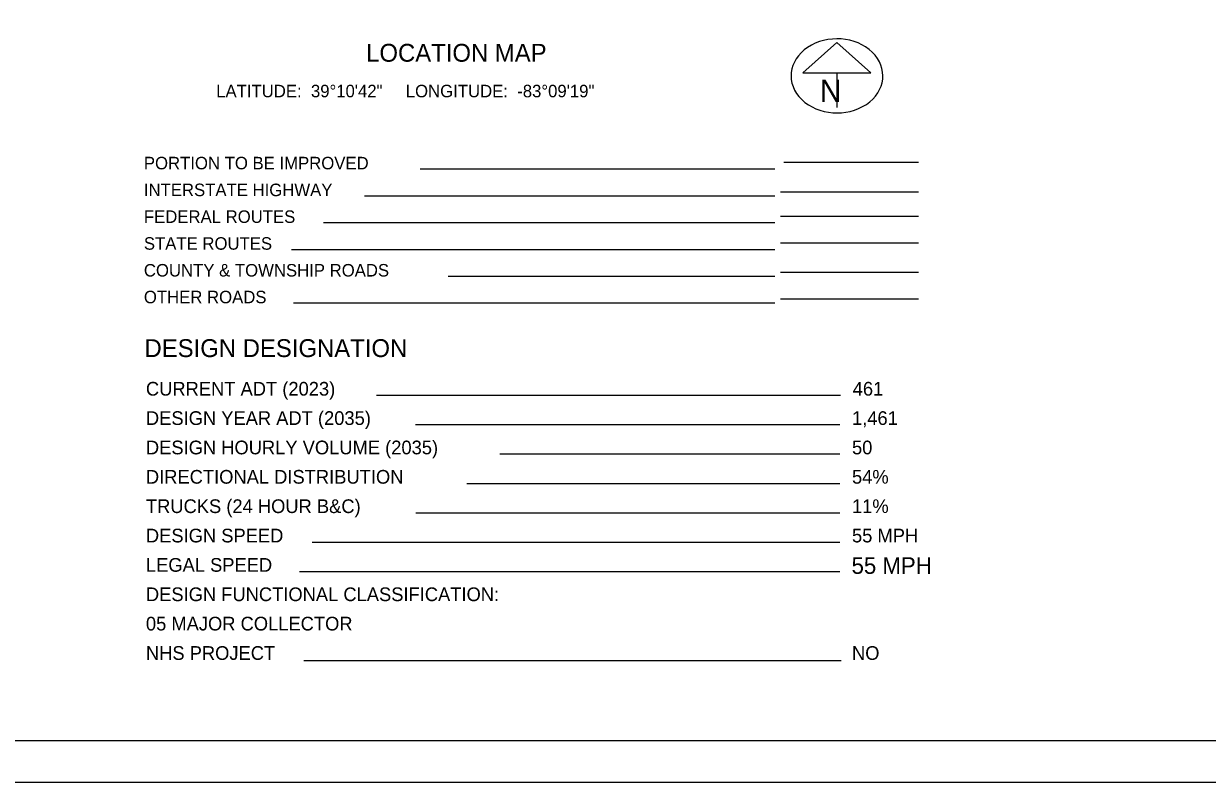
# Model space of a CAD drawing. Extents: x -139 to 835, y 0 to 440.
# Drawn here: x 62.7 to 348, y 0 to 182.8 of the extents above; entities that cross this region are included whole.
import ezdxf

# ---------------------------------------------------------------- set-up
doc = ezdxf.new("R2010")
doc.units = 0
for name, color, linetype in [('Default', 7, 'Continuous'), ('SH_Border', 7, 'Continuous'), ('SH_Cut_Line', 7, 'Continuous'), ('SH_Data', 7, 'Continuous'), ('SH_Text', 7, 'Continuous')]:
    doc.layers.add(name, color=color, linetype=linetype)

msp = doc.modelspace()

# ---------------------------------------------------------------- linework, layer by layer
at = {"layer": 'SH_Border'}
msp.add_lwpolyline([(30, 430), (670, 430), (670, 10), (30, 10)], close=True, dxfattribs=at)
at = {"layer": 'SH_Cut_Line'}
msp.add_lwpolyline([(0, 0), (680, 0), (680, 440), (0, 440)], close=True, dxfattribs=at)
at = {"layer": 'SH_Data'}
for p, q in [((258.73, 178.28), (250.53, 170.94)), ((266.93, 170.94), (258.73, 178.28)), ((250.53, 170.94), (266.93, 170.94)), ((258.73, 170.94), (258.73, 162.61)), ((258.73, 170.24), (258.73, 170.24)), ((258.73, 170.24), (258.73, 170.24)), ((245.95, 149.41), (278.4, 149.41)), ((243.75, 147.72), (158.3, 147.72)), ((243.75, 141.26), (144.86, 141.26)), ((278.4, 142.21), (245.08, 142.21)), ((243.75, 134.81), (134.99, 134.81)), ((278.4, 136.37), (245.08, 136.37)), ((278.4, 129.91), (245.08, 129.91)), ((243.75, 128.35), (127.25, 128.35)), ((278.4, 122.88), (245.08, 122.88)), ((243.75, 121.89), (165, 121.89)), ((243.75, 115.44), (127.74, 115.44)), ((278.4, 116.42), (245.08, 116.42)), ((259.55, 93.19), (147.78, 93.19)), ((259.39, 86.12), (157.16, 86.12)), ((259.39, 79.04), (177.46, 79.04)), ((259.39, 71.97), (169.5, 71.97)), ((259.39, 64.89), (157.19, 64.89)), ((259.39, 57.81), (132.22, 57.81)), ((259.39, 50.74), (129.15, 50.74)), ((259.73, 29.25), (130.22, 29.25))]:
    msp.add_line(p, q, dxfattribs=at)
msp.add_ellipse((258.73, 170.24), major_axis=(-11.06, 0), ratio=0.807538, start_param=5.406678, end_param=11.689575, dxfattribs=at)

# ---------------------------------------------------------------- texts
at = {"layer": 'Default'}
msp.add_text('55 MPH', height=4, dxfattribs=at).set_placement((262.25, 50.24))
at = {"layer": 'SH_Data'}
for s, height, p in [('N', 5.38, (254.59, 163.97)), ('DESIGN DESIGNATION', 4.3046, (91.83, 102.48))]:
    msp.add_text(s, height=height, dxfattribs=at).set_placement(p)
at = {"layer": 'SH_Text'}
for s, height, p in [('LOCATION MAP', 4.3046, (145.25, 173.65)), ('LATITUDE:  39°10\'42"     LONGITUDE:  -83°09\'19"', 3.0132, (109.11, 165.08)), ('PORTION TO BE IMPROVED', 3.0132, (91.68, 147.72)), ('INTERSTATE HIGHWAY', 3.0132, (91.68, 141.26)), ('FEDERAL ROUTES', 3.0132, (91.68, 134.81)), ('STATE ROUTES', 3.0132, (91.68, 128.35)), ('COUNTY & TOWNSHIP ROADS', 3.0132, (91.68, 121.89)), ('OTHER ROADS', 3.0132, (91.68, 115.44)), ('CURRENT ADT (2023)', 3.3019, (92.17, 93.19)), ('461', 3.302, (262.52, 93.19)), ('DESIGN YEAR ADT (2035)', 3.3019, (92.17, 86.12)), ('1,461', 3.302, (262.35, 86.12)), ('DESIGN HOURLY VOLUME (2035)', 3.3019, (92.17, 79.04)), ('50', 3.302, (262.35, 79.04)), ('DIRECTIONAL DISTRIBUTION', 3.3019, (92.17, 71.97)), ('54%', 3.302, (262.35, 71.97)), ('TRUCKS (24 HOUR B&C)', 3.3019, (92.17, 64.89)), ('11%', 3.302, (262.35, 64.89)), ('DESIGN SPEED', 3.3019, (92.17, 57.81)), ('55 MPH', 3.302, (262.35, 57.81)), ('LEGAL SPEED', 3.3019, (92.17, 50.74)), ('DESIGN FUNCTIONAL CLASSIFICATION:', 3.3019, (92.17, 43.66)), ('05 MAJOR COLLECTOR', 3.3019, (92.17, 36.59)), ('NHS PROJECT', 3.3019, (92.17, 29.51)), ('NO', 3.302, (262.35, 29.51))]:
    msp.add_text(s, height=height, dxfattribs=at).set_placement(p)

doc.saveas('drawing.dxf')
